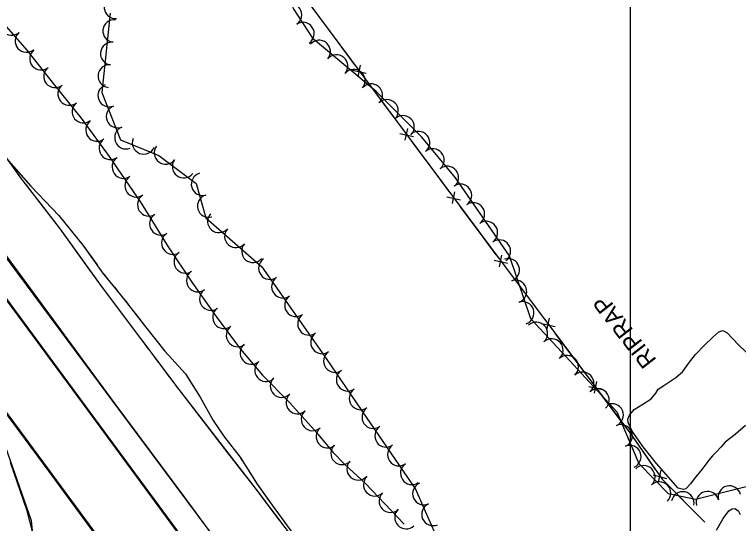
# Model space of a CAD drawing. Extents: x 353423 to 364002, y 127000 to 201942.
# Drawn here: x 360782.5 to 361038.1, y 130573.1 to 130752.7 of the extents above; entities that cross this region are included whole.
import ezdxf

# ---------------------------------------------------------------- set-up
doc = ezdxf.new("R2010")
doc.units = 0
for name, color, linetype in [('E_DTM_SlopeBottom', 7, 'Continuous'), ('E_DTM_SlopeTop', 7, 'Continuous'), ('E_FEN_Generic', 7, 'Continuous'), ('E_LAND_TreeLine', 7, 'Continuous'), ('E_MISCPROP', 7, 'Continuous'), ('E_STRUCT_WingWall', 7, 'Continuous')]:
    doc.layers.add(name, color=color, linetype=linetype)

msp = doc.modelspace()

# ---------------------------------------------------------------- linework, layer by layer
at = {"layer": 'E_DTM_SlopeBottom'}
for p, q in [((360904.61, 130734.81), (360903.73, 130730.68)), ((360901.91, 130733.02), (360906.72, 130731.96)), ((360918.54, 130710.67), (360923.36, 130709.62)), ((360921.24, 130712.46), (360920.37, 130708.33)), ((360937.88, 130690.12), (360937.01, 130685.99)), ((360935.18, 130688.32), (360940, 130687.28)), ((360954.53, 130667.78), (360953.66, 130663.65)), ((360951.83, 130665.98), (360956.65, 130664.94)), ((360968.56, 130643.7), (360973.38, 130642.67)), ((360971.25, 130645.51), (360970.4, 130641.37)), ((360987.98, 130623.23), (360987.13, 130619.09)), ((360985.29, 130621.42), (360990.11, 130620.4)), ((361007.99, 130590.25), (361012.77, 130589.02)), ((361010.76, 130591.94), (361009.73, 130587.84))]:
    msp.add_line(p, q, dxfattribs=at)
for points in [[(360846.85, 130810.08), (360908.35, 130727.26), (360954.66, 130665.09), (360999.85, 130604.94), (361003.12, 130600.39)], [(360889.92, 130752.07), (360896.67, 130742.98)], [(360896.67, 130742.98), (360902.61, 130734.99)], [(360906.53, 130729.7), (360908.35, 130727.26), (360913.29, 130720.62)], [(360913.29, 130720.62), (360919.24, 130712.64)], [(360923.17, 130707.36), (360929.94, 130698.28)], [(360929.94, 130698.28), (360935.89, 130690.29)], [(360939.82, 130685.01), (360946.58, 130675.94)], [(360946.58, 130675.94), (360952.53, 130667.95)], [(360956.47, 130662.68), (360963.27, 130653.63)], [(360963.27, 130653.63), (360969.25, 130645.67)], [(360973.21, 130640.41), (360980.01, 130631.35)], [(360980.01, 130631.35), (360985.99, 130623.39)], [(360989.94, 130618.13), (360996.74, 130609.08)], [(360996.74, 130609.08), (360999.85, 130604.94), (361002.64, 130601.06)], [(361003.12, 130600.39), (361011.14, 130588.75), (361026.25, 130573.52)], [(361003.12, 130600.39), (361008.77, 130592.19)], [(361012.83, 130587.04), (361020.81, 130579.01)], [(361020.81, 130579.01), (361026.25, 130573.52)]]:
    msp.add_lwpolyline(points, dxfattribs=at)
at = {"layer": 'E_DTM_SlopeTop'}
for points in [[(361333.55, 129917.72), (361268.46, 130006.01), (361189.85, 130112.75), (361142.67, 130176.31), (361088.86, 130249.79), (360994.04, 130376.87), (360928.62, 130465.05), (360871.56, 130543.5), (360815.21, 130618.95), (360766.71, 130684.28), (360721.66, 130745.05), (360677.21, 130805.9), (360595.4, 130915.9), (360546.5, 130984.06), (360499.99, 131045.42), (360426.96, 131144.04)], [(360419.47, 131139.59), (360478.07, 131059.84), (360541.82, 130973.68), (360588.71, 130910.37), (360647.11, 130831.47), (360699.04, 130761.76), (360750.66, 130691.62), (360805.87, 130616.86), (360864.14, 130537.84), (360910.27, 130475.6), (360951.2, 130420.07), (361004.77, 130348.23), (361046.61, 130292.04), (361097.13, 130223.94), (361149.43, 130153.39), (361185.11, 130104.98), (361238.11, 130033), (361245.88, 130022.49), (361278.08, 129978.64), (361333.1, 129905.4)], [(360915.39, 130428.25), (360885.77, 130468.28), (360854.3, 130510.8), (360823.95, 130551.75), (360794.76, 130591.46), (360773.92, 130619.47), (360751.38, 130649.91), (360722.07, 130689.97), (360692.78, 130729.59), (360658.7, 130775.33), (360626.52, 130818.94)], [(361335.19, 129902.03), (361317.97, 129925.09), (361294.2, 129957.22), (361266.66, 129994.48), (361242.03, 130027.81), (361217.11, 130061.23), (361186.78, 130102.37), (361155.57, 130144.32), (361126.8, 130183.16), (361098.06, 130221.84), (361070.02, 130259.76), (361036.43, 130304.8), (361006.19, 130345.98), (360970.52, 130394.27), (360936.12, 130440.54), (360901.22, 130487.47), (360871.26, 130528.04), (360838.83, 130571.83), (360808.58, 130612.92), (360780.05, 130651.51), (360745.78, 130697.86), (360715, 130739.66), (360684.42, 130781.1), (360659.61, 130814.18)], [(360974.98, 130403.77), (360946.02, 130442.35), (360923.23, 130473.25), (360897.45, 130508.23), (360870.85, 130544), (360842.47, 130582.65), (360817.74, 130615.85), (360781.38, 130665.29), (360748.12, 130710.1), (360720.12, 130748.06), (360677.4, 130806.22)], [(360700.18, 130641.03), (360737.14, 130600.93), (360763.85, 130570.82), (360769.77, 130566.08), (360773.6, 130563.21), (360776.55, 130561.69), (360780.15, 130561.12), (360782.23, 130561.45), (360784.62, 130562.66), (360787.38, 130564.54), (360788.44, 130567), (360788.91, 130570.68), (360788.59, 130574), (360775.19, 130612.07)], [(360770.85, 130623.99), (360920.54, 130421.12), (360968.13, 130357.32), (361021.12, 130285.55), (361062.98, 130229.08), (361129.94, 130138.98), (361193.82, 130052.53), (361225.46, 130009.93), (361276.5, 129940.65), (361332.79, 129864.55)], [(360780.45, 130560.58), (360783.15, 130561.35), (360785.46, 130562.47), (360787.87, 130564.88), (360788.58, 130566.74), (360788.88, 130570.22), (360787.07, 130577.55), (360781.17, 130594.57)]]:
    msp.add_lwpolyline(points, dxfattribs=at)
at = {"layer": 'E_FEN_Generic'}
for points in [[(361133.77, 130580.83), (361061.93, 130587.22), (361046.46, 130587.42), (361022.95, 130581.54), (361013.47, 130583.51), (361003.1, 130594.19), (360995.31, 130612.43), (360975.76, 130633.5), (360964.82, 130645.32), (360957.35, 130667.6), (360938.19, 130695.02), (360926.31, 130709.37), (360910.2, 130725.5), (360888.14, 130743.99), (360881.04, 130754.82), (360875.54, 130777.02), (360869.4, 130797.96)], [(360777, 130751.33), (360786.86, 130740.14), (360796.73, 130727.72), (360806.12, 130716.09), (360815.95, 130702.6), (360827.22, 130686.09), (360836.82, 130670.78), (360845.15, 130658.21), (360853.69, 130646.16), (360862.33, 130634.62), (360870.05, 130625.5), (360879.62, 130615.8), (360888.44, 130605.99), (360895.06, 130598.12), (360899.15, 130593.95), (360906.49, 130587.21), (360920.12, 130572.88)], [(360816.31, 130753.13), (360813.35, 130725.2), (360819.99, 130708.46), (360833.56, 130703), (360846.71, 130693.07), (360850.15, 130680.91), (360869.84, 130663.71), (360892.53, 130631.35), (360906.68, 130610.65), (360924.1, 130585.27), (360936.2, 130557.67), (360949.48, 130546.45), (360962.83, 130554.33), (360972.63, 130559.14), (360983.23, 130554.9), (360999.57, 130545.21), (361013.32, 130549.63), (361024, 130550.2), (361028.39, 130540.5), (361036.36, 130532.39), (361050.25, 130536.29)]]:
    msp.add_lwpolyline(points, dxfattribs=at)
for centre, start, end in [((360818.22, 130755.26), 95.4069, 275.3916), ((360879.97, 130752.64), 303.2678, 123.2525), ((360781.5, 130749.39), 131.4057, 311.3904), ((360817.76, 130746.88), 83.9598, 263.9444), ((360884.35, 130745.95), 303.2678, 123.2525), ((360786.78, 130743.4), 131.4057, 311.3904), ((360890.08, 130739.63), 320.0304, 140.0151), ((360816.91, 130738.93), 83.9598, 263.9444), ((360791.92, 130737.14), 128.4724, 308.457), ((360896.21, 130734.49), 320.0304, 140.0151), ((360796.89, 130730.89), 128.4724, 308.457), ((360816.07, 130730.98), 83.9598, 263.9444), ((360902.34, 130729.35), 320.0304, 140.0151), ((360908.47, 130724.22), 320.0304, 140.0151), ((360801.88, 130724.67), 128.9249, 308.9096), ((360816.03, 130724.14), 111.6248, 291.6095), ((360806.9, 130718.46), 128.9249, 308.9096), ((360818.97, 130716.7), 111.6248, 291.6095), ((360914.01, 130718.71), 314.9809, 134.9655), ((360919.67, 130713.05), 314.9809, 134.9655), ((360811.72, 130711.96), 126.0827, 306.0674), ((360821.92, 130709.27), 111.6248, 291.6095), ((360925.14, 130707.5), 309.6289, 129.6136), ((360816.43, 130705.5), 126.0827, 306.0674), ((360828.15, 130707.43), 158.0698, 338.0545), ((360835.88, 130703.86), 142.9789, 322.9636), ((360930.24, 130701.34), 309.6289, 129.6136), ((360821.02, 130698.88), 124.318, 304.3027), ((360842.27, 130699.05), 142.9789, 322.9636), ((360935.34, 130695.17), 309.6289, 129.6136), ((360825.52, 130692.28), 124.318, 304.3027), ((360848.96, 130692.82), 105.8143, 285.799), ((360939.95, 130688.85), 304.9536, 124.9383), ((360830.01, 130685.58), 122.0913, 302.076), ((360851.14, 130685.13), 105.8143, 285.799), ((360944.53, 130682.29), 304.9536, 124.9383), ((360834.25, 130678.81), 122.0913, 302.076), ((360854.7, 130679.72), 138.865, 318.8497), ((360949.11, 130675.73), 304.9536, 124.9383), ((360860.73, 130674.45), 138.865, 318.8497), ((360838.49, 130672.04), 122.0913, 302.076), ((360866.75, 130669.19), 138.865, 318.8497), ((360953.69, 130669.18), 304.9536, 124.9383), ((360842.88, 130665.42), 123.5691, 303.5538), ((360872.74, 130663.22), 125.0398, 305.0244), ((360956.83, 130662.56), 288.5515, 108.5361), ((360847.28, 130658.83), 125.3041, 305.2888), ((360877.33, 130656.67), 125.0398, 305.0244), ((360959.38, 130654.98), 288.5515, 108.5361), ((360851.89, 130652.31), 125.3041, 305.2888), ((360881.93, 130650.12), 125.0398, 305.0244), ((360961.92, 130647.4), 288.5515, 108.5361), ((360856.52, 130645.87), 126.8513, 306.836), ((360886.52, 130643.57), 125.0398, 305.0244), ((360966.76, 130640.15), 312.7792, 132.7639), ((360861.31, 130639.47), 126.8513, 306.836), ((360891.11, 130637.02), 125.0398, 305.0244), ((360866.18, 130633.3), 130.2221, 310.2067), ((360972.19, 130634.28), 312.7792, 132.7639), ((360895.69, 130630.43), 124.3548, 304.3395), ((360977.63, 130628.41), 312.8743, 132.859), ((360871.34, 130627.2), 130.2221, 310.2067), ((360900.2, 130623.83), 124.3548, 304.3395), ((360983.07, 130622.55), 312.8743, 132.859), ((360876.82, 130621.61), 134.6479, 314.6326), ((360988.51, 130616.68), 312.8743, 132.859), ((360882.44, 130615.79), 131.9629, 311.9476), ((360904.72, 130617.23), 124.3548, 304.3395), ((360909.23, 130610.63), 124.4814, 304.4661), ((360993.49, 130611.38), 293.1173, 113.1019), ((360887.78, 130609.85), 131.9629, 311.9476), ((360996.63, 130604.02), 293.1173, 113.1019), ((360893.05, 130603.76), 130.0886, 310.0733), ((360913.76, 130604.03), 124.4814, 304.4661), ((360898.22, 130597.88), 134.4247, 314.4094), ((360918.28, 130597.44), 124.4814, 304.4661), ((360999.77, 130596.66), 293.1173, 113.1019), ((360903.9, 130592.43), 137.4464, 317.4311), ((360922.81, 130590.84), 124.4814, 304.4661), ((361004.67, 130589.56), 314.1646, 134.1492), ((360909.76, 130586.8), 133.5793, 313.564), ((361010.25, 130583.82), 314.1646, 134.1492), ((360927.09, 130583.66), 113.6836, 293.6682), ((361034.95, 130582.38), 14.0524, 194.0371), ((360915.27, 130581.01), 133.5793, 313.564), ((361018.46, 130580.33), 348.2822, 168.2668), ((361027.19, 130580.44), 14.0524, 194.0371), ((360930.3, 130576.34), 113.6836, 293.6682), ((360920.78, 130575.22), 133.5793, 313.564)]:
    msp.add_arc(centre, 4, start, end, dxfattribs=at)
at = {"layer": 'E_LAND_TreeLine'}
msp.add_line((361000, 129000), (361000, 131500), dxfattribs=at)
at = {"layer": 'E_MISCPROP'}
for points in [[(361040.64, 130607.67), (361036.96, 130604.49), (361033.42, 130601.82), (361031.9, 130600.02), (361030.38, 130598.4), (361029, 130597.03), (361027.65, 130595.44), (361025.21, 130592.17), (361022.43, 130588.87), (361021.25, 130587.15), (361019.55, 130585.28), (361018.73, 130585.09), (361016.81, 130585.59), (361013.38, 130589.41), (361009.21, 130594.32), (361004.47, 130600.17), (361000.66, 130605.63), (360999.18, 130608.74), (360999.09, 130609.86), (360999.62, 130611.35), (361001.36, 130613.3), (361004.31, 130615.26), (361007.34, 130617.09), (361008.92, 130619.1), (361009.74, 130620.45), (361011.81, 130621.84), (361014.27, 130623.39), (361016.03, 130624.57), (361018.34, 130626.6), (361020.87, 130629.99), (361022.98, 130632.75), (361026.16, 130636.08), (361029.05, 130638.82), (361031.18, 130640.76), (361032.61, 130641.19), (361034.17, 130640.4), (361038.03, 130636.31), (361040.86, 130633.54)], [(361030.35, 130570.71), (361032.73, 130574.84), (361034.76, 130577.56), (361035.95, 130578.29), (361036.9, 130578.39), (361037.49, 130578.07), (361038.11, 130577.4)], [(361038.11, 130577.4), (361038.72, 130576.26)]]:
    msp.add_lwpolyline(points, dxfattribs=at)
at = {"layer": 'E_STRUCT_WingWall'}
for points in [[(360564.35, 130994.96), (360591.08, 130958.39), (360617.07, 130919.63), (360639.79, 130889.58), (360661.49, 130860.97), (360681.66, 130834.2), (360697.6, 130810.86), (360722.75, 130777.24), (360743.2, 130749.8), (360768.63, 130717.47), (360784.71, 130695.06), (360798.65, 130676.94), (360813.5, 130656.32), (360840.51, 130620.35), (360867.84, 130585.1), (360898.21, 130544.91), (360920.78, 130515.95), (360944.48, 130484.11), (360969.8, 130448.78), (360992.09, 130420.31)], [(360774.09, 130708.44), (360779.58, 130702.06), (360788.3, 130692.08), (360793.39, 130686.8)], [(360779.58, 130702.06), (360788.3, 130692.08), (360798.26, 130681.75), (360806.62, 130671.31), (360813.67, 130661.61), (360821.42, 130652.05), (360828.78, 130642.5), (360835.57, 130633.88), (360842.9, 130625.88), (360848.12, 130617.66), (360852.73, 130609.45), (360856.65, 130603.6), (360862.16, 130596.52), (360868.24, 130586.98), (360873.48, 130579.53), (360880.78, 130569.6)], [(360782.96, 130697.51), (360784.16, 130695.84)], [(360786.64, 130692.56), (360787.89, 130690.93)], [(360790.4, 130687.67), (360798.65, 130676.94), (360808.17, 130663.72)], [(360793.39, 130686.8), (360798.26, 130681.75), (360806.62, 130671.31), (360811.68, 130664.35)], [(360808.17, 130663.72), (360813.5, 130656.32), (360825.93, 130639.76)], [(360814.06, 130661.13), (360815.32, 130659.58)], [(360817.83, 130656.47), (360819.09, 130654.92)], [(360821.61, 130651.8), (360822.83, 130650.22)], [(360825.27, 130647.05), (360828.78, 130642.5), (360835.57, 130633.88), (360842.9, 130625.88), (360843.66, 130624.68)], [(360828.41, 130636.47), (360829.64, 130634.83)], [(360832.11, 130631.54), (360833.35, 130629.9)], [(360835.82, 130626.61), (360837.05, 130624.96)], [(360843.66, 130624.68), (360848.12, 130617.66), (360852.73, 130609.45), (360856.65, 130603.6), (360859.25, 130600.26)], [(360839.52, 130621.67), (360840.51, 130620.35), (360857.77, 130598.09)], [(360857.77, 130598.09), (360867.84, 130585.1), (360875.91, 130574.42)], [(360861.71, 130597.11), (360862.16, 130596.52), (360862.84, 130595.46)], [(360864.99, 130592.08), (360866.06, 130590.4)], [(360868.21, 130587.02), (360868.24, 130586.98), (360869.36, 130585.39)], [(360871.66, 130582.11), (360873.48, 130579.53), (360880.78, 130569.6), (360886.56, 130561.4), (360888.63, 130558.6)]]:
    msp.add_lwpolyline(points, dxfattribs=at)

# ---------------------------------------------------------------- texts
at = {"layer": 'E_MISCPROP'}
msp.add_text('RIPRAP', height=6, rotation=127.9537, dxfattribs=at).set_placement((361009.42, 130630.82))

doc.saveas('drawing.dxf')
